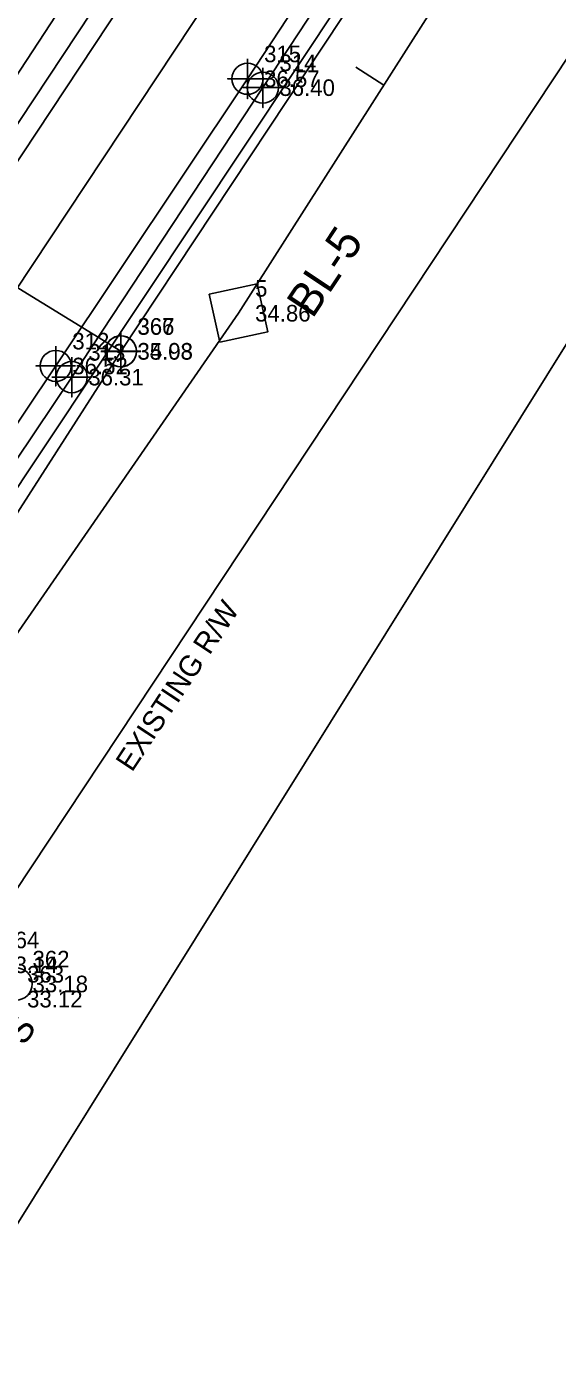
# Model space of a CAD drawing. Extents: x 2603627 to 2605187, y 896619 to 899063.
# Drawn here: x 2604761.6 to 2604841.7, y 898327.7 to 898527.2 of the extents above; entities that cross this region are included whole.
import ezdxf

# ---------------------------------------------------------------- set-up
doc = ezdxf.new("R2010")
doc.units = 0
for name, color, linetype in [('CTL Supplemental Horizontal and Vertical CELL', 7, 'Continuous'), ('CTL Supplemental Horizontal and Vertical Cogo Elevation', 7, 'Continuous'), ('CTL Supplemental Horizontal and Vertical Cogo Number', 7, 'Continuous'), ('CTL Supplemental Horizontal and Vertical Text', 7, 'Continuous'), ('Exist Horizontal Alignment', 7, 'Continuous'), ('Exist Horizontal Baseline Alignment', 7, 'Continuous'), ('Exist Horizontal Baseline Alignment Tick small', 7, 'Continuous'), ('Exist Other Culture Sign Cogo Elevation', 7, 'Continuous'), ('Exist Other Culture Sign Cogo Number', 7, 'Continuous'), ('Exist Other Culture Sign Text', 7, 'Continuous'), ('Exist Right of Way Line', 7, 'Continuous'), ('Exist Right of Way Line Text', 7, 'Continuous'), ('Exist Roads EOP', 7, 'Continuous'), ('Exist Roads EOP Cogo Elevation', 7, 'Continuous'), ('Exist Roads EOP Cogo Number', 7, 'Continuous'), ('Exist Roads EOP Cogo Point CELL', 7, 'Continuous'), ('Exist Roads EOT', 7, 'Continuous'), ('Exist Roads EOT Cogo Elevation', 7, 'Continuous'), ('Exist Roads EOT Cogo Number', 7, 'Continuous'), ('Exist Roads EOT Cogo Point CELL', 7, 'Continuous'), ('Exist Utilities Power Pole CELL', 7, 'Continuous'), ('Exist Utilities Power Pole Cogo Elevation', 7, 'Continuous'), ('Exist Utilities Power Pole Cogo Number', 7, 'Continuous'), ('Exist Utilities Telephone UG Cable SUE LOS C', 7, 'Continuous'), ('Exist Utilities Water UG Line SUE LOS B', 7, 'Continuous'), ('Exist Utilities Water UG Line SUE LOS B Cogo Elevation', 7, 'Continuous'), ('Exist Utilities Water UG Line SUE LOS B Cogo Number', 7, 'Continuous'), ('Exist Utilities Water UG Line SUE LOS B Cogo Point CELL', 7, 'Continuous'), ('Exist Vegetation Woods Line', 7, 'Continuous')]:
    doc.layers.add(name, color=color, linetype=linetype)

# ---------------------------------------------------------------- blocks, each defined once
blk = doc.blocks.new('EXIST ROADS EOT COGO POINT')
at = {"layer": 'Exist Roads EOT Cogo Point CELL'}
blk.add_lwpolyline([(0, 0.06), (0, -0.06), (0, 0), (-0.06, 0), (0.06, 0)], dxfattribs=at)
blk.add_circle((0, 0), 0.0469, dxfattribs=at)
blk = doc.blocks.new('EXIST ROADS EOP COGO POINT')
at = {"layer": 'Exist Roads EOP Cogo Point CELL'}
blk.add_lwpolyline([(0, 0.06), (0, -0.06), (0, 0), (0.06, 0), (-0.06, 0)], dxfattribs=at)
blk.add_circle((0, 0), 0.0469, dxfattribs=at)
blk = doc.blocks.new('EXIST UTILITIES WATER UG LINE SUE LOS B COGO POINT')
at = {"layer": 'Exist Utilities Water UG Line SUE LOS B Cogo Point CELL'}
blk.add_lwpolyline([(0, 0.06), (0, -0.06), (0, 0), (0.06, 0), (-0.06, 0)], dxfattribs=at)
blk.add_circle((0, 0), 0.0469, dxfattribs=at)
blk = doc.blocks.new('CTL SUPPLEMENTAL HORIZONTAL AND VERTICAL')
at = {"layer": 'CTL Supplemental Horizontal and Vertical CELL'}
blk.add_line((0, 0), (0, 0), dxfattribs=at)
blk.add_lwpolyline([(-0.1043, 0.0004), (0.0005, 0.1052), (0.1055, 0.0002), (0.0007, -0.1047)], close=True, dxfattribs=at)

msp = doc.modelspace()

# ---------------------------------------------------------------- linework, layer by layer
at = {"layer": 'Exist Horizontal Alignment'}
msp.add_line((2604681.44, 898368.79), (2605041.11, 898911.74), dxfattribs=at)
at = {"layer": 'Exist Horizontal Baseline Alignment'}
for p, q in [((2604793.6, 898483.9), (2605028.26, 898852.56)), ((2604544.96, 898124.44), (2604793.6, 898483.9))]:
    msp.add_line(p, q, dxfattribs=at)
at = {"layer": 'Exist Horizontal Baseline Alignment Tick small'}
msp.add_line((2604815.5, 898518.31), (2604811.28, 898520.99), dxfattribs=at)
at = {"layer": 'Exist Right of Way Line'}
msp.add_line((2604723.13, 898341.18), (2605082.79, 898884.13), dxfattribs=at)
at = {"layer": 'Exist Roads EOP'}
for points in [[(2604577.96, 898237.27), (2604606.45, 898281.24), (2604633.89, 898322.5), (2604662.45, 898365.47), (2604690.62, 898408.06), (2604717.29, 898448.09), (2604745.46, 898490.11), (2604773.6, 898532.6), (2604800.88, 898573.95), (2604828.34, 898615.46), (2604855.1, 898656.15), (2604883.53, 898699.09), (2604911.29, 898740.95), (2604939.38, 898783.41), (2604966.33, 898824.04), (2604993.38, 898865.27), (2605022.2, 898908.38), (2605029.46, 898919.46)], [(2604713.86, 898392.44), (2604740.28, 898432.25), (2604768.45, 898474.26), (2604797.27, 898517.92), (2604823.93, 898558.47), (2604851.31, 898599.84), (2604878.52, 898641.09), (2604906.84, 898683.65), (2604934.68, 898725.71), (2604962.63, 898767.92), (2604989.32, 898808.49), (2605016.42, 898849.59), (2605045.34, 898893.33), (2605052.55, 898904.16)]]:
    msp.add_lwpolyline(points, dxfattribs=at)
at = {"layer": 'Exist Roads EOT'}
for points in [[(2604580.65, 898235.67), (2604609.23, 898279.3), (2604636.66, 898320.72), (2604665.18, 898363.91), (2604693.37, 898406.36), (2604719.95, 898446.05), (2604748, 898488.34), (2604776.15, 898530.84), (2604803.5, 898572.3), (2604830.95, 898613.91), (2604857.58, 898654.47), (2604886.02, 898697.38), (2604913.86, 898739.33), (2604942.03, 898781.72), (2604969.06, 898822.38), (2604996.07, 898863.44), (2605024.73, 898906.73), (2605032, 898917.78)], [(2604598.04, 898223.4), (2604627.23, 898267.23), (2604654.64, 898308.57), (2604683.28, 898352.01), (2604711.27, 898394.14), (2604737.98, 898434.05), (2604766.04, 898475.94), (2604794.96, 898519.26), (2604821.61, 898559.82), (2604848.89, 898601.4), (2604876.12, 898642.73), (2604904.4, 898685.35), (2604932.33, 898727.23), (2604960.29, 898769.49), (2604987.32, 898810.19), (2605014.12, 898850.95), (2605043.08, 898894.89), (2605050.2, 898905.72)]]:
    msp.add_lwpolyline(points, dxfattribs=at)
at = {"layer": 'Exist Utilities Power Pole CELL'}
msp.add_circle((2604760.04, 898382.73), 2.45, dxfattribs=at)
at = {"layer": 'Exist Utilities Telephone UG Cable SUE LOS C'}
for p, q in [((2604753.32, 898447.21), (2604850.74, 898593.69)), ((2604580.04, 898245.37), (2604795.48, 898573.63))]:
    msp.add_line(p, q, dxfattribs=at)
at = {"layer": 'Exist Utilities Water UG Line SUE LOS B'}
for points in [[(2604590.41, 898183.07), (2604608.13, 898210.78), (2604631.33, 898247.72), (2604631.98, 898248.77), (2604637.93, 898260.9), (2604650.01, 898281.75), (2604670.13, 898312.66), (2604706.14, 898370.49), (2604744.2, 898428.79), (2604775.85, 898478.14), (2604817.62, 898541.22), (2604844.76, 898580.18), (2604876.2, 898627.22), (2604907.55, 898675.15), (2604931.69, 898711.47), (2604963.51, 898758.63), (2604991.08, 898800.9), (2605022.23, 898847.26), (2605044.13, 898880.13), (2605057.71, 898900.74)], [(2604775.86, 898478.17), (2604748.57, 898494.9), (2604732.86, 898504.6)]]:
    msp.add_lwpolyline(points, dxfattribs=at)
at = {"layer": 'Exist Vegetation Woods Line'}
msp.add_lwpolyline([(2604653.24, 898142.95), (2604632.09, 898155.82), (2604674.87, 898231.68), (2604758.69, 898344.01), (2604864.62, 898513.8)], dxfattribs=at)

# ---------------------------------------------------------------- block references
at = {"layer": 'CTL Supplemental Horizontal and Vertical CELL', "xscale": 50, "yscale": 49.99999999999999, "rotation": 57.44453205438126}
msp.add_blockref('CTL SUPPLEMENTAL HORIZONTAL AND VERTICAL', (2604793.6, 898483.9), dxfattribs=at)
at = {"layer": 'Exist Roads EOP Cogo Point CELL', "xscale": 50, "yscale": 50}
for p in [(2604797.27, 898517.92), (2604768.45, 898474.26)]:
    msp.add_blockref('EXIST ROADS EOP COGO POINT', p, dxfattribs=at)
at = {"layer": 'Exist Roads EOT Cogo Point CELL', "xscale": 50, "yscale": 50}
for p in [(2604794.96, 898519.26), (2604766.04, 898475.94)]:
    msp.add_blockref('EXIST ROADS EOT COGO POINT', p, dxfattribs=at)
at = {"layer": 'Exist Utilities Water UG Line SUE LOS B Cogo Point CELL', "xscale": 50, "yscale": 50}
for p in [(2604775.85, 898478.14), (2604775.87, 898478.16)]:
    msp.add_blockref('EXIST UTILITIES WATER UG LINE SUE LOS B COGO POINT', p, dxfattribs=at)

# ---------------------------------------------------------------- texts
at = {"layer": 'CTL Supplemental Horizontal and Vertical Cogo Elevation'}
msp.add_text('34.86', height=2.5, dxfattribs=at).set_placement((2604796.1, 898482.65))
at = {"layer": 'CTL Supplemental Horizontal and Vertical Cogo Number'}
msp.add_text('5', height=2.5, dxfattribs=at).set_placement((2604796.1, 898486.4))
at = {"layer": 'CTL Supplemental Horizontal and Vertical Text'}
msp.add_text('BL-5', height=5, rotation=56.4094, dxfattribs=at).set_placement((2604804.75, 898482.94))
at = {"layer": 'Exist Other Culture Sign Cogo Elevation'}
for s, p in [('33.14', (2604757.98, 898384.37)), ('33.12', (2604761.72, 898379.19))]:
    msp.add_text(s, height=2.5, dxfattribs=at).set_placement(p)
at = {"layer": 'Exist Other Culture Sign Cogo Number'}
for s, p in [('364', (2604757.98, 898388.12)), ('363', (2604761.72, 898382.94))]:
    msp.add_text(s, height=2.5, dxfattribs=at).set_placement(p)
at = {"layer": 'Exist Other Culture Sign Text'}
msp.add_text('S', height=4, rotation=56.4094, dxfattribs=at).set_placement((2604761.29, 898373.27))
at = {"layer": 'Exist Right of Way Line Text'}
msp.add_text('EXISTING R/W', height=3.2, rotation=56.4785, dxfattribs=at).set_placement((2604777.54, 898414.57))
at = {"layer": 'Exist Roads EOP Cogo Elevation'}
for s, p in [('36.40', (2604799.77, 898516.67)), ('36.31', (2604770.95, 898473.01))]:
    msp.add_text(s, height=2.5, dxfattribs=at).set_placement(p)
at = {"layer": 'Exist Roads EOP Cogo Number'}
for s, p in [('314', (2604799.77, 898520.42)), ('313', (2604770.95, 898476.76))]:
    msp.add_text(s, height=2.5, dxfattribs=at).set_placement(p)
at = {"layer": 'Exist Roads EOT Cogo Elevation'}
for s, p in [('36.57', (2604797.46, 898518.01)), ('36.52', (2604768.54, 898474.69))]:
    msp.add_text(s, height=2.5, dxfattribs=at).set_placement(p)
at = {"layer": 'Exist Roads EOT Cogo Number'}
for s, p in [('315', (2604797.46, 898521.76)), ('312', (2604768.54, 898478.44))]:
    msp.add_text(s, height=2.5, dxfattribs=at).set_placement(p)
at = {"layer": 'Exist Utilities Power Pole Cogo Elevation'}
msp.add_text('33.18', height=2.5, dxfattribs=at).set_placement((2604762.54, 898381.48))
at = {"layer": 'Exist Utilities Power Pole Cogo Number'}
msp.add_text('362', height=2.5, dxfattribs=at).set_placement((2604762.54, 898385.23))
at = {"layer": 'Exist Utilities Water UG Line SUE LOS B Cogo Elevation'}
for s, p in [('35.03', (2604778.35, 898476.89)), ('34.98', (2604778.37, 898476.91))]:
    msp.add_text(s, height=2.5, dxfattribs=at).set_placement(p)
at = {"layer": 'Exist Utilities Water UG Line SUE LOS B Cogo Number'}
for s, p in [('366', (2604778.35, 898480.64)), ('367', (2604778.37, 898480.66))]:
    msp.add_text(s, height=2.5, dxfattribs=at).set_placement(p)

doc.saveas('drawing.dxf')
